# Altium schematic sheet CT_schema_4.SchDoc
size 287 x 169 mm
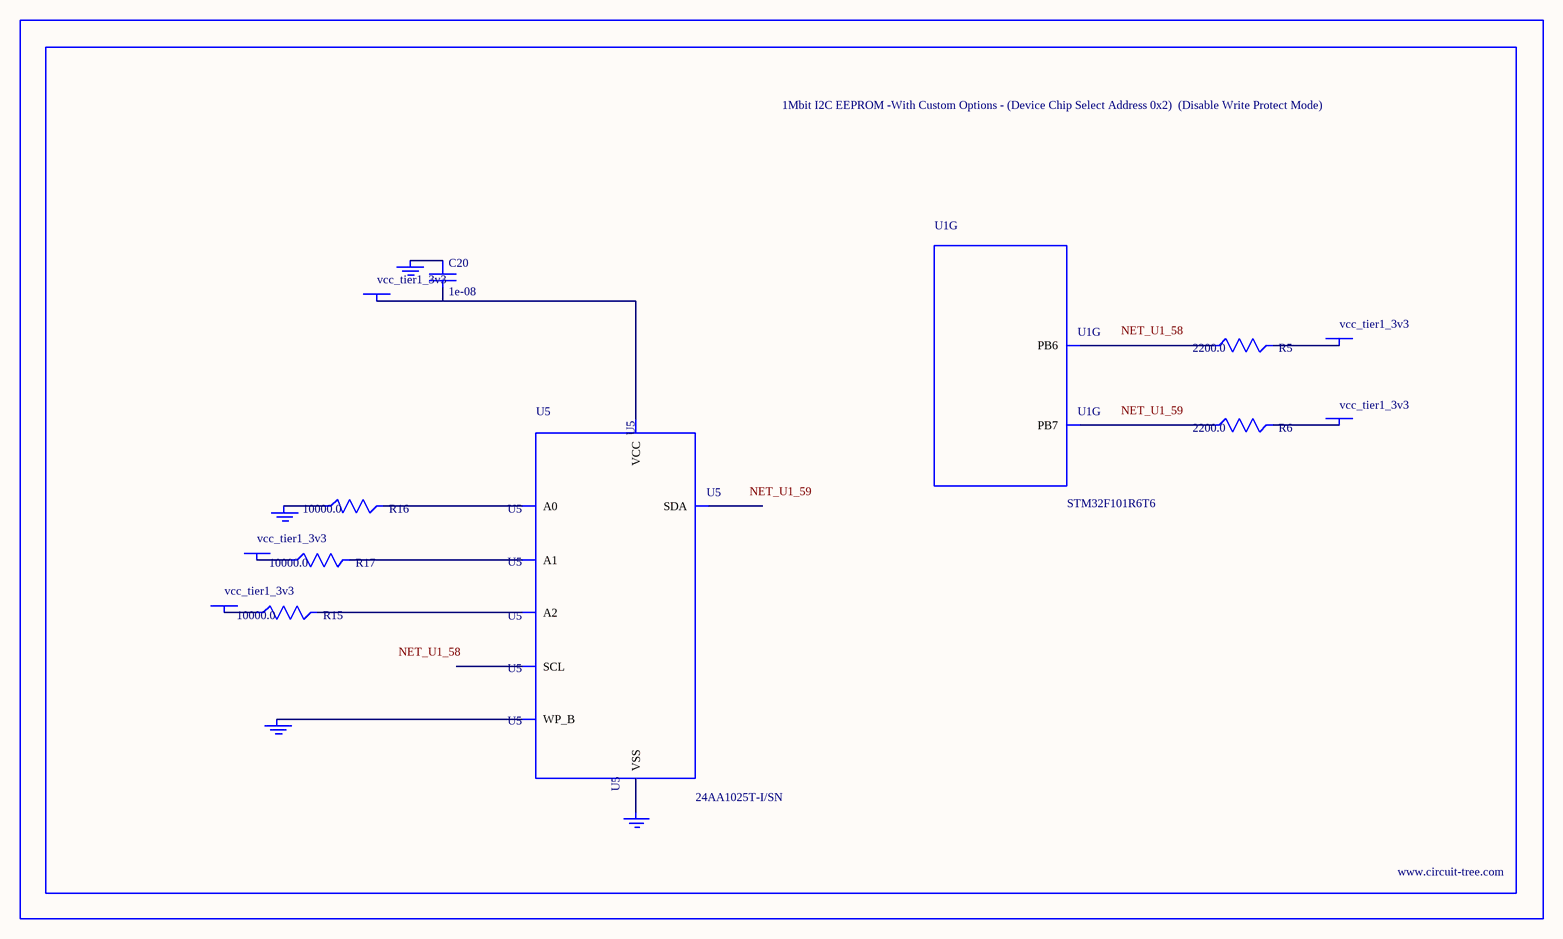
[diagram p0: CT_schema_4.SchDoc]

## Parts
BORDER3  (no value)
C20  1e-08  [C0402]
GND_INSTANCE_3_0  (no value)
GND_INSTANCE_3_1  (no value)
GND_INSTANCE_3_2  (no value)
GND_INSTANCE_3_3  (no value)
POWER_INSTANCE_3_0  vcc_tier1_3v3
POWER_INSTANCE_3_1  vcc_tier1_3v3
POWER_INSTANCE_3_2  vcc_tier1_3v3
POWER_INSTANCE_3_3  vcc_tier1_3v3
POWER_INSTANCE_3_4  vcc_tier1_3v3
R5  2200.0  [R0603]
R6  2200.0  [R0603]
R15  10000.0  [R0603]
R16  10000.0  [R0603]
R17  10000.0  [R0603]
U1  STM32F101R6T6  [LQFP64]  (part G of 7)
U5  24AA1025T-I/SN  [SOIC-8]

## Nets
NetC20_1: C20.1 GND_INSTANCE_3_2.0(GND)
NetC20_2: C20.2 POWER_INSTANCE_3_2.0(PWR) U5.8(VCC)
NetGND_INSTANCE_3_0_0: GND_INSTANCE_3_0.0(GND) R16.1
NetGND_INSTANCE_3_1_0: GND_INSTANCE_3_1.0(GND) U5.7(WP_B)
NetGND_INSTANCE_3_3_0: GND_INSTANCE_3_3.0(GND) U5.4(VSS)
NetPOWER_INSTANCE_3_0_0: POWER_INSTANCE_3_0.0(PWR) R17.1
NetPOWER_INSTANCE_3_1_0: POWER_INSTANCE_3_1.0(PWR) R15.1
NetPOWER_INSTANCE_3_3_0: POWER_INSTANCE_3_3.0(PWR) R5.2
NetPOWER_INSTANCE_3_4_0: POWER_INSTANCE_3_4.0(PWR) R6.2
NetR5_1: R5.1 U1.58(PB6)
NetR6_1: R6.1 U1.59(PB7)
NetR15_2: R15.2 U5.3(A2)
NetR16_2: R16.2 U5.1(A0)
NetR17_2: R17.2 U5.2(A1)

Not connected (* = marked no-connect by the designer): U5 5(SDA) 6(SCL)

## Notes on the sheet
- Labels drawn without touching a wire or pin: NET_U1_58, NET_U1_59

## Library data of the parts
BORDER3 = BORDER_PAGE3
C20 = C0402C103K3RAC
GND_INSTANCE_3_0-GND_INSTANCE_3_3 = GND
POWER_INSTANCE_3_0-POWER_INSTANCE_3_4 = PWR
R5 R6 = RC0603JR-072K2L
R15-R17 = RC0603JR-0710KL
